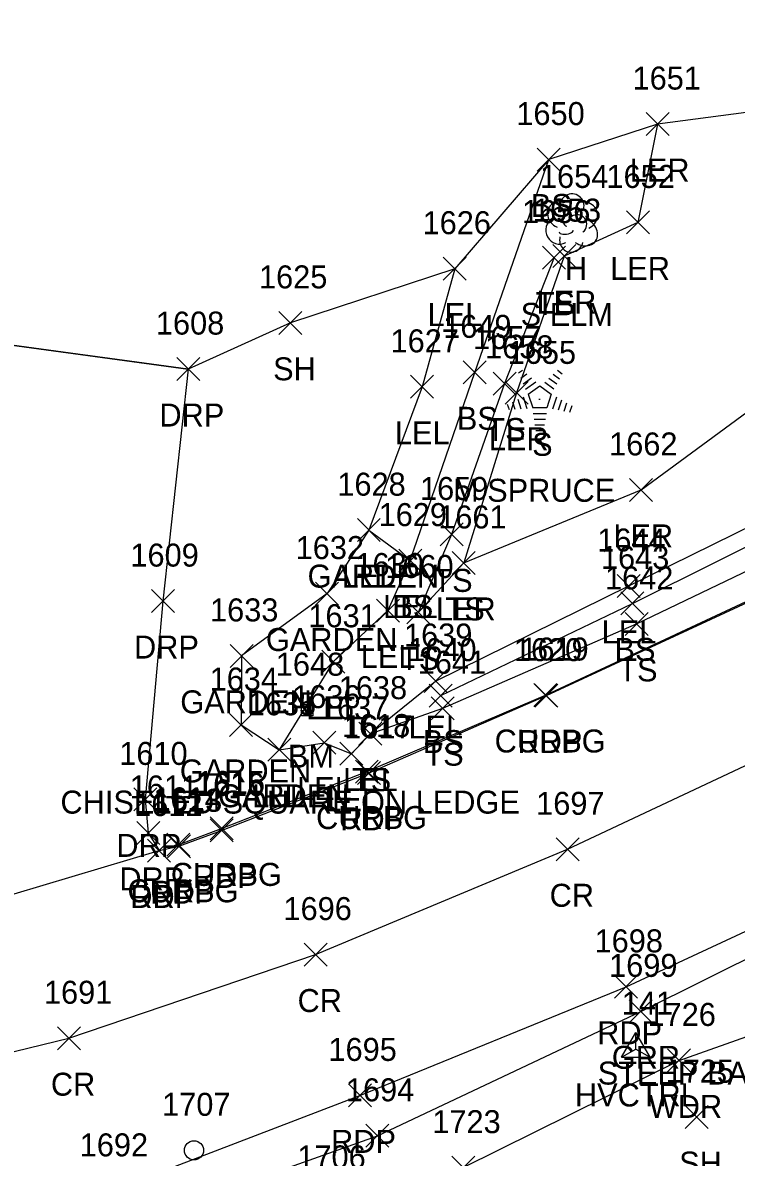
# Model space of a CAD drawing. Extents: x 1638344 to 1639591, y 610835 to 612202.
# Drawn here: x 1638469.9 to 1638532, y 611608.8 to 611707.5 of the extents above; entities that cross this region are included whole.
import ezdxf

# ---------------------------------------------------------------- set-up
doc = ezdxf.new("R2010")
doc.units = 0
for name, color, linetype in [('C_A', 7, 'Continuous'), ('C_C', 7, 'Continuous'), ('C_I', 7, 'Continuous'), ('CPBM', 7, 'Continuous'), ('CPSM', 7, 'Continuous'), ('L_A', 7, 'Continuous'), ('L_C', 7, 'Continuous'), ('L_I', 7, 'Continuous'), ('L_TIC', 7, 'Continuous'), ('LAPB', 7, 'Continuous'), ('LARO', 7, 'Continuous'), ('LAWA', 7, 'Continuous'), ('LELB', 7, 'Continuous'), ('LSOGP', 7, 'Continuous'), ('LTC', 7, 'Continuous'), ('LTD', 7, 'Continuous'), ('P_A', 7, 'Continuous'), ('P_I', 7, 'Continuous'), ('P_TIC', 7, 'Continuous'), ('PET', 7, 'Continuous'), ('PRC', 7, 'Continuous'), ('R_A', 7, 'Continuous'), ('R_I', 7, 'Continuous'), ('R_TIC', 7, 'Continuous'), ('RC', 7, 'Continuous'), ('RDP', 7, 'Continuous'), ('RGR', 7, 'Continuous'), ('S_I', 7, 'Continuous'), ('U_I', 7, 'Continuous'), ('USMH', 7, 'Continuous')]:
    doc.layers.add(name, color=color, linetype=linetype)

msp = doc.modelspace()

# ---------------------------------------------------------------- linework, layer by layer
at = {"layer": 'CPBM'}
for p, q in [((1638494.167, 611647.186), (1638494.167, 611648.186)), ((1638494.167, 611648.186), (1638495.167, 611648.186)), ((1638495.167, 611648.186), (1638495.167, 611647.186)), ((1638495.167, 611647.186), (1638494.167, 611647.186)), ((1638494.67, 611647.687), (1638494.67, 611647.687)), ((1638494.67, 611647.687), (1638494.67, 611647.687))]:
    msp.add_line(p, q, dxfattribs=at)
at = {"layer": 'CPSM'}
for p, q in [((1638522.017, 611617.486), (1638523.267, 611619.651)), ((1638524.517, 611617.486), (1638523.267, 611619.651)), ((1638523.268, 611618.207), (1638523.267, 611619.651)), ((1638522.017, 611617.486), (1638523.268, 611618.207)), ((1638522.017, 611617.486), (1638524.517, 611617.486)), ((1638523.268, 611618.207), (1638523.268, 611618.207)), ((1638523.268, 611618.207), (1638524.517, 611617.486))]:
    msp.add_line(p, q, dxfattribs=at)
at = {"layer": 'L_TIC'}
for points in [[(1638524.151, 611697.678), (1638526.151, 611699.678)], [(1638526.151, 611697.678), (1638524.151, 611699.678)], [(1638514.691, 611694.593), (1638516.691, 611696.593)], [(1638516.691, 611694.593), (1638514.691, 611696.593)], [(1638522.449, 611689.119), (1638524.449, 611691.119)], [(1638524.449, 611689.119), (1638522.449, 611691.119)], [(1638515.149, 611686.062), (1638517.149, 611688.062)], [(1638517.149, 611686.062), (1638515.149, 611688.062)], [(1638516.039, 611686.19), (1638518.039, 611688.19)], [(1638518.039, 611686.19), (1638516.039, 611688.19)], [(1638506.499, 611685.096), (1638508.499, 611687.096)], [(1638508.499, 611685.096), (1638506.499, 611687.096)], [(1638492.208, 611680.381), (1638494.208, 611682.381)], [(1638494.208, 611680.381), (1638492.208, 611682.381)], [(1638508.246, 611676.077), (1638510.246, 611678.077)], [(1638510.246, 611676.077), (1638508.246, 611678.077)], [(1638503.656, 611674.818), (1638505.656, 611676.818)], [(1638505.656, 611674.818), (1638503.656, 611676.818)], [(1638510.844, 611675.101), (1638512.844, 611677.101)], [(1638512.844, 611675.101), (1638510.844, 611677.101)], [(1638511.883, 611674.295), (1638513.883, 611676.295)], [(1638513.883, 611674.295), (1638511.883, 611676.295)], [(1638522.725, 611665.847), (1638524.725, 611667.847)], [(1638524.725, 611665.847), (1638522.725, 611667.847)], [(1638499.027, 611662.348), (1638501.027, 611664.348)], [(1638501.027, 611662.348), (1638499.027, 611664.348)], [(1638499.027, 611662.348), (1638501.027, 611664.348)], [(1638501.027, 611662.348), (1638499.027, 611664.348)], [(1638506.232, 611661.975), (1638508.232, 611663.975)], [(1638508.232, 611661.975), (1638506.232, 611663.975)], [(1638502.628, 611659.701), (1638504.628, 611661.701)], [(1638504.628, 611659.701), (1638502.628, 611661.701)], [(1638502.628, 611659.701), (1638504.628, 611661.701)], [(1638504.628, 611659.701), (1638502.628, 611661.701)], [(1638507.286, 611659.494), (1638509.286, 611661.494)], [(1638509.286, 611659.494), (1638507.286, 611661.494)], [(1638507.286, 611659.494), (1638509.286, 611661.494)], [(1638509.286, 611659.494), (1638507.286, 611661.494)], [(1638521.645, 611657.49), (1638523.645, 611659.49)], [(1638523.645, 611657.49), (1638521.645, 611659.49)], [(1638495.4, 611656.832), (1638497.4, 611658.832)], [(1638497.4, 611656.832), (1638495.4, 611658.832)], [(1638521.968, 611655.977), (1638523.968, 611657.977)], [(1638523.968, 611655.977), (1638521.968, 611657.977)], [(1638500.685, 611655.356), (1638502.685, 611657.356)], [(1638502.685, 611655.356), (1638500.685, 611657.356)], [(1638503.326, 611655.185), (1638505.326, 611657.185)], [(1638505.326, 611655.185), (1638503.326, 611657.185)], [(1638522.323, 611654.191), (1638524.323, 611656.191)], [(1638524.323, 611654.191), (1638522.323, 611656.191)], [(1638487.947, 611651.409), (1638489.947, 611653.409)], [(1638489.947, 611651.409), (1638487.947, 611653.409)], [(1638495.936, 611650.898), (1638497.936, 611652.898)], [(1638497.936, 611650.898), (1638495.936, 611652.898)], [(1638504.839, 611649.222), (1638506.839, 611651.222)], [(1638506.839, 611649.222), (1638504.839, 611651.222)], [(1638505.28, 611647.951), (1638507.28, 611649.951)], [(1638507.28, 611647.951), (1638505.28, 611649.951)], [(1638505.453, 611646.854), (1638507.453, 611648.854)], [(1638507.453, 611646.854), (1638505.453, 611648.854)], [(1638487.908, 611645.396), (1638489.908, 611647.396)], [(1638489.908, 611645.396), (1638487.908, 611647.396)], [(1638499.15, 611644.641), (1638501.15, 611646.641)], [(1638501.15, 611644.641), (1638499.15, 611646.641)], [(1638499.15, 611644.641), (1638501.15, 611646.641)], [(1638501.15, 611644.641), (1638499.15, 611646.641)], [(1638491.23, 611643.24), (1638493.23, 611645.24)], [(1638493.23, 611643.24), (1638491.23, 611645.24)], [(1638491.23, 611643.24), (1638493.23, 611645.24)], [(1638493.23, 611643.24), (1638491.23, 611645.24)], [(1638495.147, 611643.858), (1638497.147, 611645.858)], [(1638497.147, 611643.858), (1638495.147, 611645.858)], [(1638497.516, 611642.895), (1638499.516, 611644.895)], [(1638499.516, 611642.895), (1638497.516, 611644.895)], [(1638526.028, 611616.214), (1638528.028, 611618.214)], [(1638528.028, 611616.214), (1638526.028, 611618.214)], [(1638527.547, 611611.281), (1638529.547, 611613.281)], [(1638529.547, 611611.281), (1638527.547, 611613.281)], [(1638507.245, 611606.886), (1638509.245, 611608.886)], [(1638509.245, 611606.886), (1638507.245, 611608.886)]]:
    msp.add_lwpolyline(points, dxfattribs=at)
at = {"layer": 'LAPB'}
msp.add_lwpolyline([(1638500.027, 611663.348), (1638496.4, 611657.832), (1638488.947, 611652.409), (1638488.908, 611646.396), (1638492.23, 611644.24)], dxfattribs=at)
at = {"layer": 'LARO'}
for points in [[(1638507.499, 611686.096), (1638504.656, 611675.818), (1638500.027, 611663.348), (1638503.628, 611660.701), (1638501.685, 611656.356), (1638496.936, 611651.898), (1638492.23, 611644.24), (1638496.147, 611644.858), (1638498.516, 611643.895), (1638500.15, 611645.641), (1638505.839, 611650.222), (1638522.645, 611658.49), (1638552.024, 611672.95), (1638564.411, 611673.299), (1638582.298, 611683.818), (1638600.645, 611694.729), (1638614.45, 611704.873)], [(1638525.151, 611698.678), (1638523.449, 611690.119), (1638517.039, 611687.19), (1638512.883, 611675.295), (1638508.286, 611660.494), (1638523.725, 611666.847), (1638534.91, 611675.056), (1638547.906, 611682.838), (1638553.288, 611683.216), (1638570.67, 611686.127)]]:
    msp.add_lwpolyline(points, dxfattribs=at)
at = {"layer": 'LAWA'}
msp.add_lwpolyline([(1638355.934, 611578.146), (1638379.624, 611581.437), (1638409.495, 611585.936), (1638444.058, 611588.569), (1638475.657, 611594.367), (1638498.86, 611601.357), (1638508.245, 611607.886), (1638527.028, 611617.214), (1638546.505, 611624.113), (1638573.22, 611641.376), (1638594.595, 611652.363), (1638613.43, 611662.838), (1638623.727, 611665.865), (1638642.742, 611667.089)], dxfattribs=at)
at = {"layer": 'LELB'}
for points in [[(1638503.628, 611660.701), (1638509.246, 611677.077), (1638515.691, 611695.593)], [(1638516.149, 611687.062), (1638511.844, 611676.101), (1638507.232, 611662.975), (1638504.326, 611656.185), (1638508.286, 611660.494)], [(1638500.15, 611645.641), (1638506.453, 611647.854), (1638523.323, 611655.191), (1638553.745, 611669.777), (1638564.411, 611673.299)], [(1638506.28, 611648.951), (1638522.968, 611656.977), (1638552.842, 611671.856), (1638564.411, 611673.299)]]:
    msp.add_lwpolyline(points, dxfattribs=at)
at = {"layer": 'LSOGP'}
msp.add_lwpolyline([(1638544.314, 611701.186), (1638525.151, 611698.678), (1638515.691, 611695.593), (1638507.499, 611686.096), (1638493.208, 611681.381), (1638484.312, 611677.361), (1638479.191, 611678.053), (1638474.069, 611678.745), (1638468.947, 611679.437), (1638463.825, 611680.129), (1638447.11, 611680.16), (1638446.375, 611676.119), (1638445.334, 611671.295), (1638445.002, 611669.783), (1638442.954, 611659.181), (1638442.394, 611656.587), (1638440.297, 611645.344), (1638415.664, 611649.528), (1638379.03, 611639.471), (1638358.66, 611627.132), (1638355.83, 611619.706), (1638355.881, 611616.997), (1638356.118, 611602.692)], dxfattribs=at)
at = {"layer": 'LTC'}
for p, q in [((1638513.047, 611677.022), (1638513.401, 611677.28)), ((1638513.256, 611676.557), (1638513.785, 611676.941)), ((1638516.074, 611676.914), (1638516.623, 611676.515)), ((1638516.445, 611677.263), (1638516.864, 611676.958)), ((1638513.466, 611676.091), (1638514.17, 611676.602)), ((1638513.675, 611675.625), (1638514.554, 611676.263)), ((1638513.9, 611675.17), (1638514.912, 611675.905)), ((1638514.912, 611675.905), (1638515.909, 611675.18)), ((1638515.332, 611676.218), (1638516.141, 611675.629)), ((1638515.703, 611676.566), (1638516.382, 611676.072)), ((1638512.99, 611674.735), (1638513.261, 611673.899)), ((1638513.445, 611674.951), (1638513.776, 611673.932)), ((1638513.9, 611675.17), (1638514.287, 611673.977)), ((1638515.909, 611675.18), (1638515.518, 611673.977)), ((1638516.346, 611674.909), (1638516.008, 611673.869)), ((1638516.791, 611674.659), (1638516.503, 611673.774)), ((1638512.079, 611674.302), (1638512.231, 611673.834)), ((1638512.535, 611674.518), (1638512.746, 611673.867)), ((1638515.518, 611673.977), (1638514.287, 611673.977)), ((1638517.235, 611674.409), (1638516.998, 611673.679)), ((1638517.68, 611674.158), (1638517.493, 611673.584)), ((1638515.479, 611673.477), (1638514.335, 611673.477)), ((1638515.395, 611672.977), (1638514.407, 611672.977)), ((1638515.312, 611672.477), (1638514.48, 611672.477)), ((1638515.228, 611671.977), (1638514.553, 611671.977))]:
    msp.add_line(p, q, dxfattribs=at)
at = {"layer": 'LTD'}
msp.add_line((1638517.663, 611690.121), (1638517.663, 611690.121), dxfattribs=at)
msp.add_line((1638517.663, 611690.121), (1638517.663, 611690.121), dxfattribs=at)
msp.add_arc((1638517.709, 611691.555), 1.047, 335.52715, 180.95627, dxfattribs=at)
for centre, major_axis, ratio, start_param, end_param in [((1638516.871, 611690.788), (1.21, -0.512), 0.895232, 1.570796, 4.712389), ((1638517.454, 611690.579), (-0.208, -0.792), 0.645439, 3.141593, 6.283185), ((1638518.704, 611690.705), (-1.141, -0.483), 0.949671, 1.570796, 4.712389), ((1638516.58, 611689.413), (0.584, -1.042), 0.959034, 3.141593, 6.283185), ((1638518.163, 611689.955), (-0.5, 0.667), 0.989748, 3.141593, 6.283185), ((1638517.205, 611689.371), (-0.625, -0.083), 0.423636, 0, 3.141593), ((1638518.663, 611689.288), (-1.09, 0.792), 0.841452, 1.570796, 4.712389), ((1638517.663, 611688.621), (0.265, 1.061), 0.942809, 1.570796, 4.712389)]:
    msp.add_ellipse(centre, major_axis=major_axis, ratio=ratio, start_param=start_param, end_param=end_param, dxfattribs=at)
at = {"layer": 'P_TIC'}
for points in [[(1638514.475, 611647.95), (1638516.475, 611649.95)], [(1638516.475, 611647.95), (1638514.475, 611649.95)], [(1638499.055, 611641.229), (1638501.055, 611643.229)], [(1638501.055, 611641.229), (1638499.055, 611643.229)], [(1638486.217, 611636.218), (1638488.217, 611638.218)], [(1638488.217, 611636.218), (1638486.217, 611638.218)], [(1638480.778, 611634.472), (1638482.778, 611636.472)], [(1638482.778, 611634.472), (1638480.778, 611636.472)], [(1638482.493, 611634.844), (1638484.493, 611636.844)], [(1638484.493, 611634.844), (1638482.493, 611636.844)], [(1638516.33, 611634.581), (1638518.33, 611636.581)], [(1638518.33, 611634.581), (1638516.33, 611636.581)], [(1638494.393, 611625.423), (1638496.393, 611627.423)], [(1638496.393, 611625.423), (1638494.393, 611627.423)], [(1638521.413, 611622.617), (1638523.413, 611624.617)], [(1638523.413, 611622.617), (1638521.413, 611624.617)], [(1638472.926, 611618.145), (1638474.926, 611620.145)], [(1638474.926, 611618.145), (1638472.926, 611620.145)], [(1638498.254, 611613.17), (1638500.254, 611615.17)], [(1638500.254, 611613.17), (1638498.254, 611615.17)]]:
    msp.add_lwpolyline(points, dxfattribs=at)
at = {"layer": 'PET'}
for points in [[(1638356.392, 611589.511), (1638387.532, 611591.223), (1638422.642, 611595.339), (1638450.599, 611600.068), (1638477.607, 611605.868), (1638499.254, 611614.17), (1638522.413, 611623.617), (1638545.698, 611634.447), (1638565.585, 611644.415), (1638587.926, 611655.836), (1638616.735, 611670.619), (1638633.38, 611678.503), (1638639.773, 611680.788), (1638643.668, 611682.223), (1638643.826, 611693.958), (1638643.72, 611707.497), (1638631.783, 611704.69), (1638616.315, 611698.489), (1638583.677, 611682.572)], [(1638355.97, 611616.931), (1638384.535, 611618.591), (1638398.864, 611619.61), (1638400.74, 611618.429), (1638405.64, 611618.566), (1638407.823, 611620.304), (1638423.276, 611621.83), (1638446.809, 611626.112), (1638452.746, 611627.381), (1638459.034, 611628.698), (1638481.778, 611635.472), (1638483.493, 611635.844), (1638487.217, 611637.218), (1638500.055, 611642.229), (1638515.475, 611648.95), (1638537.758, 611659.278), (1638554.291, 611667.168), (1638564.39, 611672.354), (1638583.677, 611682.572)]]:
    msp.add_lwpolyline(points, dxfattribs=at)
at = {"layer": 'PRC'}
msp.add_lwpolyline([(1638356.118, 611602.692), (1638388.659, 611605.003), (1638420.617, 611608.455), (1638449.138, 611613.12), (1638473.926, 611619.145), (1638495.393, 611626.423), (1638517.33, 611635.581), (1638540.468, 611646.456), (1638560.014, 611656.083), (1638583.711, 611667.643), (1638612.695, 611681.655), (1638628.785, 611688.734), (1638636.085, 611691.336), (1638643.826, 611693.958)], dxfattribs=at)
at = {"layer": 'R_TIC'}
for points in [[(1638483.312, 611676.361), (1638485.312, 611678.361)], [(1638485.312, 611676.361), (1638483.312, 611678.361)], [(1638481.104, 611656.177), (1638483.104, 611658.177)], [(1638483.104, 611656.177), (1638481.104, 611658.177)], [(1638514.391, 611648.003), (1638516.391, 611650.003)], [(1638516.391, 611648.003), (1638514.391, 611650.003)], [(1638498.854, 611641.344), (1638500.854, 611643.344)], [(1638500.854, 611641.344), (1638498.854, 611643.344)], [(1638479.565, 611638.923), (1638481.565, 611640.923)], [(1638481.565, 611638.923), (1638479.565, 611640.923)], [(1638486.214, 611636.398), (1638488.214, 611638.398)], [(1638488.214, 611636.398), (1638486.214, 611638.398)], [(1638479.829, 611636.005), (1638481.829, 611638.005)], [(1638481.829, 611636.005), (1638479.829, 611638.005)], [(1638480.778, 611634.472), (1638482.778, 611636.472)], [(1638482.778, 611634.472), (1638480.778, 611636.472)], [(1638482.443, 611634.971), (1638484.443, 611636.971)], [(1638484.443, 611634.971), (1638482.443, 611636.971)], [(1638522.685, 611620.483), (1638524.685, 611622.483)], [(1638524.685, 611620.483), (1638522.685, 611622.483)], [(1638499.768, 611609.656), (1638501.768, 611611.656)], [(1638501.768, 611609.656), (1638499.768, 611611.656)]]:
    msp.add_lwpolyline(points, dxfattribs=at)
at = {"layer": 'RC'}
msp.add_lwpolyline([(1638483.443, 611635.971), (1638487.214, 611637.398), (1638499.854, 611642.344), (1638515.391, 611649.003), (1638537.647, 611659.378), (1638554.263, 611667.323), (1638564.351, 611672.542), (1638583.686, 611682.969), (1638601.506, 611692.913), (1638615.139, 611700.875), (1638623.045, 611705.268)], dxfattribs=at)
at = {"layer": 'RDP'}
msp.add_lwpolyline([(1638459.034, 611628.698), (1638459.547, 611632.651), (1638460.801, 611650.264), (1638460.985, 611652.553), (1638463.825, 611680.129), (1638484.312, 611677.361), (1638482.104, 611657.177), (1638480.565, 611639.923), (1638480.829, 611637.005), (1638481.778, 611635.472)], dxfattribs=at)
at = {"layer": 'RGR'}
msp.add_lwpolyline([(1638356.811, 611587.459), (1638387.614, 611589.769), (1638422.622, 611593.649), (1638451.307, 611597.607), (1638478.216, 611602.625), (1638500.768, 611610.656), (1638523.685, 611621.483), (1638546.213, 611632.671), (1638566.507, 611643.028), (1638588.48, 611654.339), (1638617.531, 611669.474), (1638633.838, 611677.478), (1638639.915, 611680.195), (1638642.705, 611681.409)], dxfattribs=at)
at = {"layer": 'USMH'}
for p, q in [((1638484.81, 611609.395), (1638484.81, 611609.395)), ((1638485.644, 611609.395), (1638485.644, 611609.395))]:
    msp.add_line(p, q, dxfattribs=at)
msp.add_circle((1638484.81, 611609.395), 0.833, dxfattribs=at)

# ---------------------------------------------------------------- texts
at = {"layer": 'C_A'}
for s, p in [('BM', (1638492.985, 611642.687)), ('HVCTRL', (1638517.961, 611613.207))]:
    msp.add_text(s, height=2, dxfattribs=at).set_placement(p)
at = {"layer": 'C_C'}
msp.add_text('CHISELED SQUARE ON LEDGE', height=2, dxfattribs=at).set_placement((1638473.19, 611638.687))
at = {"layer": 'C_I'}
for s, p in [('1648', (1638491.93, 611650.687)), ('141', (1638522.04, 611621.207))]:
    msp.add_text(s, height=2, dxfattribs=at).set_placement(p)
at = {"layer": 'L_A'}
for s, p in [('LER', (1638522.733, 611693.678)), ('BS', (1638514.132, 611690.593)), ('H', (1638517.096, 611685.121)), ('LER', (1638521.031, 611685.119)), ('TS', (1638514.559, 611682.062)), ('LER', (1638514.622, 611682.19)), ('LEL', (1638505.136, 611681.096)), ('SH', (1638491.697, 611676.381)), ('BS', (1638507.687, 611672.077)), ('LEL', (1638502.294, 611670.818)), ('TS', (1638510.253, 611671.101)), ('LER', (1638510.466, 611670.295)), ('S', (1638514.237, 611669.814)), ('LER', (1638521.308, 611661.847)), ('GARDEN', (1638494.696, 611658.348)), ('LEL', (1638497.664, 611658.348)), ('TS', (1638505.642, 611657.975)), ('LEL', (1638501.266, 611655.701)), ('BS', (1638502.069, 611655.701)), ('LER', (1638505.869, 611655.494)), ('TS', (1638506.695, 611655.494)), ('LEL', (1638520.283, 611653.49)), ('GARDEN', (1638491.069, 611652.832)), ('BS', (1638521.409, 611651.977)), ('LEL', (1638499.323, 611651.356)), ('TS', (1638502.736, 611651.185)), ('TS', (1638521.733, 611650.191)), ('GARDEN', (1638483.616, 611647.409)), ('LEL', (1638494.574, 611646.898)), ('LEL', (1638503.477, 611645.222)), ('BS', (1638504.721, 611643.951)), ('TS', (1638504.863, 611642.854)), ('GARDEN', (1638483.577, 611641.396)), ('LEL', (1638497.788, 611640.641)), ('TS', (1638498.559, 611640.641)), ('GARDEN', (1638486.899, 611639.24)), ('LEL', (1638489.868, 611639.24)), ('LEL', (1638493.784, 611639.858)), ('LEL', (1638496.154, 611638.895)), ('WDR', (1638524.39, 611612.214)), ('SH', (1638527.035, 611607.281))]:
    msp.add_text(s, height=2, dxfattribs=at).set_placement(p)
at = {"layer": 'L_C'}
for s, p in [('S ELM', (1638513.238, 611681.121)), ('M SPRUCE', (1638507.355, 611665.814)), ('STEEP BANK GOES DOWN TO RIVER', (1638519.946, 611615.113))]:
    msp.add_text(s, height=2, dxfattribs=at).set_placement(p)
at = {"layer": 'L_I'}
for s, p in [('1651', (1638522.977, 611701.678)), ('1650', (1638512.865, 611698.593)), ('1654', (1638514.923, 611693.121)), ('1652', (1638520.708, 611693.119)), ('1656', (1638513.354, 611690.062)), ('1653', (1638514.299, 611690.19)), ('1626', (1638504.703, 611689.096)), ('1625', (1638490.468, 611684.381)), ('1649', (1638506.498, 611680.077)), ('1627', (1638501.916, 611678.818)), ('1657', (1638509.104, 611679.101)), ('1658', (1638510.143, 611678.295)), ('1655', (1638512.111, 611677.814)), ('1662', (1638520.938, 611669.847)), ('1628', (1638497.287, 611666.348)), ('1628', (1638497.287, 611666.348)), ('1659', (1638504.484, 611665.975)), ('1629', (1638500.88, 611663.701)), ('1629', (1638500.88, 611663.701)), ('1661', (1638506.066, 611663.494)), ('1661', (1638506.066, 611663.494)), ('1632', (1638493.66, 611660.832)), ('1644', (1638519.905, 611661.49)), ('1643', (1638520.227, 611659.977)), ('1630', (1638498.858, 611659.356)), ('1660', (1638501.452, 611659.185)), ('1642', (1638520.583, 611658.191)), ('1633', (1638486.207, 611655.409)), ('1631', (1638494.763, 611654.898)), ('1639', (1638503.091, 611653.222)), ('1640', (1638503.453, 611651.951)), ('1641', (1638504.28, 611650.854)), ('1634', (1638486.168, 611649.396)), ('1638', (1638497.41, 611648.641)), ('1638', (1638497.41, 611648.641)), ('1635', (1638489.49, 611647.24)), ('1635', (1638489.49, 611647.24)), ('1636', (1638493.351, 611647.858)), ('1637', (1638495.776, 611646.895)), ('1726', (1638524.28, 611620.214)), ('1725', (1638525.854, 611615.281)), ('1723', (1638505.552, 611610.886))]:
    msp.add_text(s, height=2, dxfattribs=at).set_placement(p)
at = {"layer": 'LTC'}
msp.add_text('.', height=1.037, rotation=270, dxfattribs=at).set_placement((1638514.794, 611674.918))
at = {"layer": 'P_A'}
for s, p in [('RDP', (1638512.963, 611643.95)), ('RDP', (1638497.543, 611637.229)), ('RDP', (1638484.705, 611632.218)), ('RDP', (1638479.266, 611630.472)), ('RDP', (1638480.981, 611630.844)), ('CR', (1638515.763, 611630.581)), ('CR', (1638493.826, 611621.423)), ('RDP', (1638519.901, 611618.617)), ('CR', (1638472.359, 611614.145)), ('RDP', (1638496.742, 611609.17))]:
    msp.add_text(s, height=2, dxfattribs=at).set_placement(p)
at = {"layer": 'P_I'}
for s, p in [('1620', (1638512.648, 611651.95)), ('1617', (1638497.882, 611645.229)), ('1616', (1638484.988, 611640.218)), ('1612', (1638479.605, 611638.472)), ('1613', (1638481.32, 611638.844)), ('1697', (1638514.589, 611638.581)), ('1696', (1638492.598, 611629.423)), ('1698', (1638519.672, 611626.617)), ('1691', (1638471.753, 611622.145)), ('1695', (1638496.513, 611617.17)), ('1692', (1638474.866, 611608.868))]:
    msp.add_text(s, height=2, dxfattribs=at).set_placement(p)
at = {"layer": 'R_A'}
for s, p in [('DRP', (1638481.801, 611672.361)), ('DRP', (1638479.592, 611652.177)), ('CURBG', (1638510.974, 611644.003)), ('CURBG', (1638495.437, 611637.344)), ('DRP', (1638478.053, 611634.923)), ('CURBG', (1638482.797, 611632.398)), ('DRP', (1638478.317, 611632.005)), ('CURBG', (1638479.026, 611630.971)), ('DRP', (1638479.266, 611630.472)), ('GRR', (1638521.173, 611616.483))]:
    msp.add_text(s, height=2, dxfattribs=at).set_placement(p)
at = {"layer": 'R_I'}
for s, p in [('1608', (1638481.494, 611680.361)), ('1609', (1638479.277, 611660.177)), ('1619', (1638513.21, 611652.003)), ('1618', (1638497.681, 611645.344)), ('1610', (1638478.305, 611642.923)), ('1615', (1638485.041, 611640.398)), ('1611', (1638479.222, 611640.005)), ('1612', (1638479.605, 611638.472)), ('1614', (1638481.27, 611638.971)), ('1699', (1638520.937, 611624.483)), ('1694', (1638498.028, 611613.656))]:
    msp.add_text(s, height=2, dxfattribs=at).set_placement(p)
at = {"layer": 'S_I'}
msp.add_text('1706', height=2, dxfattribs=at).set_placement((1638493.806, 611607.821))
at = {"layer": 'U_I'}
msp.add_text('1707', height=2, dxfattribs=at).set_placement((1638482.039, 611612.395))

doc.saveas('drawing.dxf')
